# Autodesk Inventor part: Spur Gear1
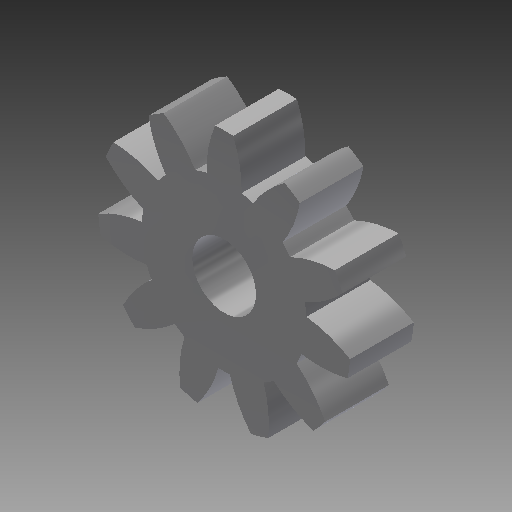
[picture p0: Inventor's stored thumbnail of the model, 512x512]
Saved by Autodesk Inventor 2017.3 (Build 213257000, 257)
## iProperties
Created: 2020-03
Part Number: Spur Gear1
Material: Steel
Document SubType Name: Modeling
Designer: Tim_G
Categories: <?xml version="1.0" encoding="UTF-16"?> <MemberInstance><Categories><FamilyTemplate><FamilyTemplateParameter ValueType="xs:double" Id="1" ObjectReferenceKey="da
Density: 1 g/cm^3
Appearance: Steel
CustomPartVersion: 1
Author: Tim_G
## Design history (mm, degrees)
sketch "Sketch1"
  geometry: C1 r 9.899 at (0, 0)
  constraints: 1 centre point
  dimensions: "d0" = 19.79817 diameter of C1 (= da_da)
extrude "Extrusion1" new body sketch "Sketch1" distance "d1" = 5 (= da_b); taper "d2" = 0 deg
workplane "Work Plane2"
sketch "Sketch2"
  geometry: C1 r 9.899 at (0, 0) reference; C2 r 8.376 at (0, 0)
  constraints: 1 centre point, 1 coincident
  dimensions: "d3" = 16.75229 diameter of C2 (= da_dw)
feature "Pitch Diameter" sketch "Sketch2" dims "d4" = 10, "d5" = 0
workplane "Work Plane8"
workplane "Work Plane9"
feature "Spur Gear" dims "da_b" = 5, "da_d" = 16.75229, "da_aw" = 22.84404, "da_da" = 19.79817, "da_df" = 12.94495, "da_dw" = 16.75229, angle "da_beta" = 0 deg, "da_lefttooth" = 0, "da_righttooth" = 0
sketch "Sketch3"
  geometry: C1 r 2.5 at (0, 0); 1 further point
  constraints: 1 centre point, 1 coincident
  dimensions: "d49" = 5 diameter of C1
extrude "Extrusion2" cut sketch "Sketch3" distance "d50" = 5; taper "d51" = 0 deg
body "Solid1"
body "Srf1"
other parameters: "d16" = 22.84404 (= da_aw), "d17" = 0, "d34" = 2.85599 (computed from da_z), "d39" = 0, "d41" = 0, "d43" = 22.84404 (= da_aw), "d46" = 22.84404 (= da_aw), "d47" = 0, "d48" = 0
